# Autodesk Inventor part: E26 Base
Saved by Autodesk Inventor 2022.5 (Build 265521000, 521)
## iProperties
Created: 2025-02
Part Number: E26 Base
Material: Generic
Document SubType Name: Modeling
Designer: AdminForWorker
Density: 1 g/cm^3
Appearance: Default
Title: E26 Base
Author: AdminForWorker
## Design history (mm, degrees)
feature "E26 Base"
body "Solid1"
